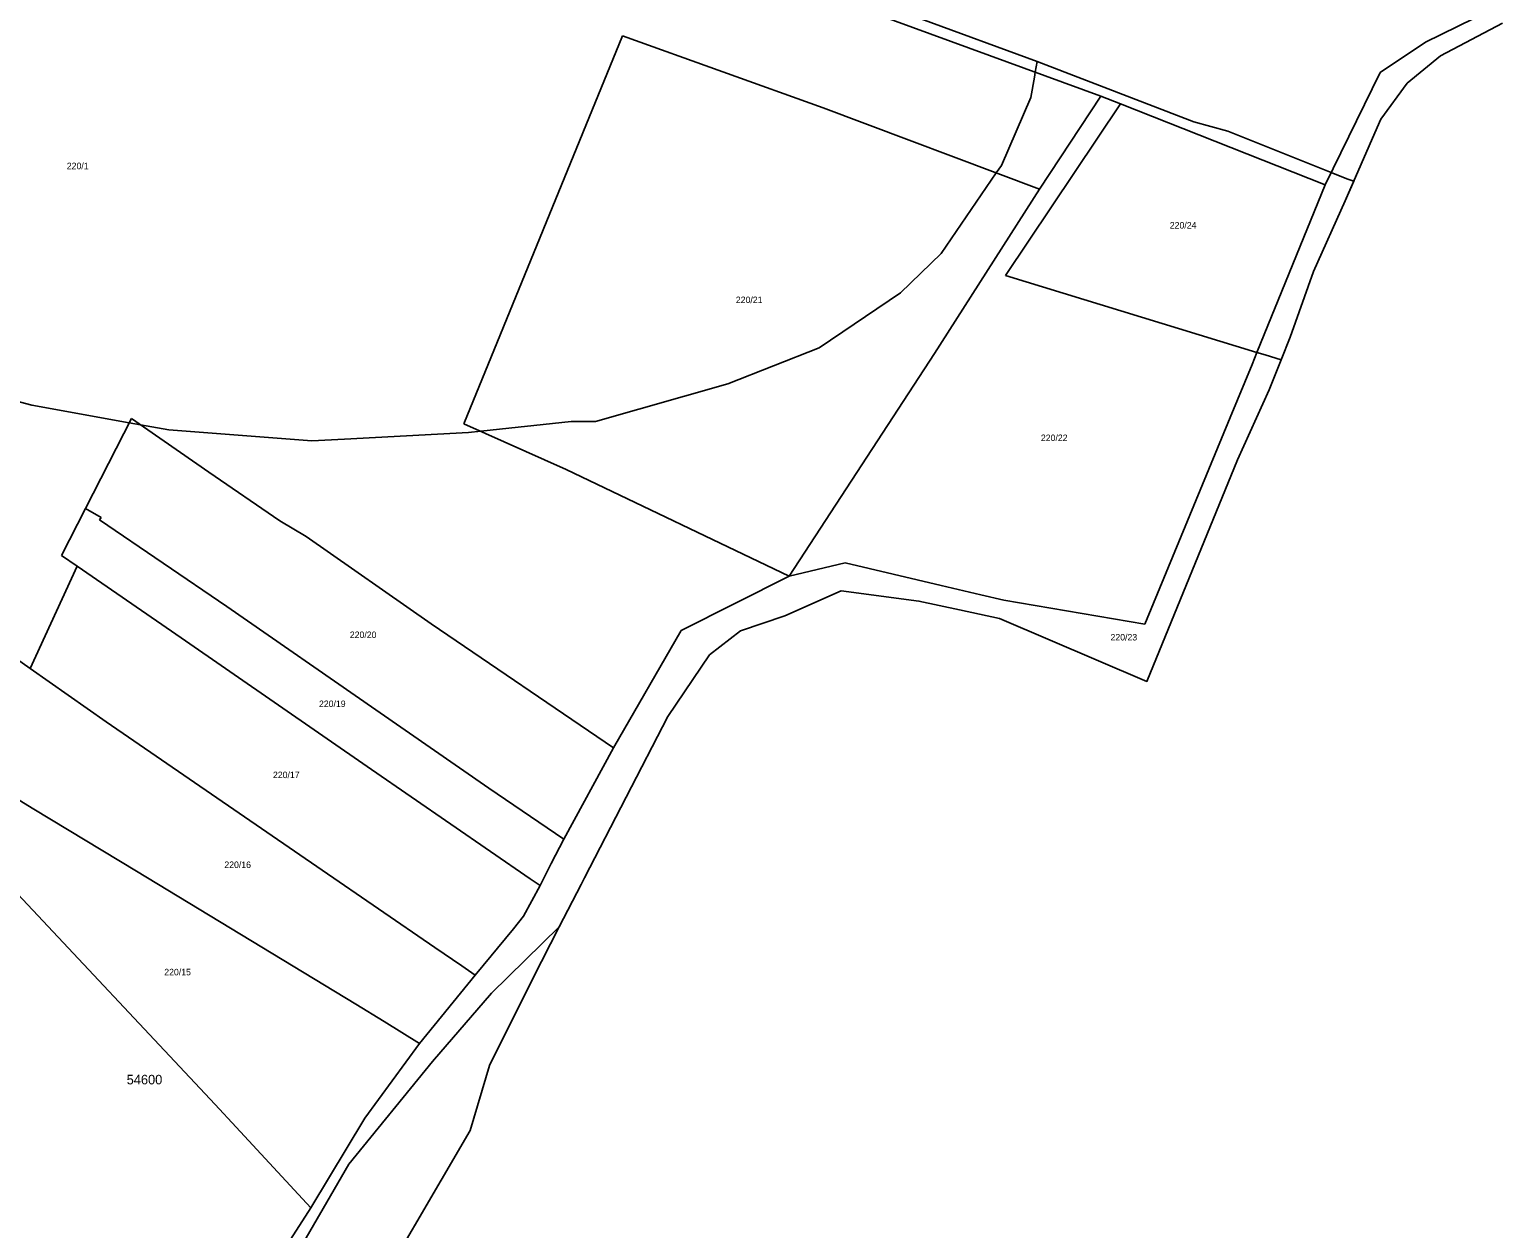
# Model space of a CAD drawing. Extents: x -749173 to -746119, y -1132678 to -1130338.
# Drawn here: x -746740.4 to -746355, y -1131280.2 to -1130967.3 of the extents above; entities that cross this region are included whole.
import ezdxf

# ---------------------------------------------------------------- set-up
doc = ezdxf.new("R2010")
doc.units = 0
for name, color, linetype in [('Vrstva 1', 7, 'Continuous'), ('Vrstva 13', 7, 'Continuous'), ('Vrstva 18', 7, 'Continuous'), ('Vrstva 52', 7, 'Continuous'), ('Vrstva 53', 7, 'Continuous'), ('Vrstva 6', 7, 'Continuous')]:
    doc.layers.add(name, color=color, linetype=linetype)

msp = doc.modelspace()

# ---------------------------------------------------------------- linework, layer by layer
at = {"layer": 'Vrstva 1'}
for points in [[(-746534.39, -1130957.75), (-746460.82, -1130984.67)], [(-746376.11, -1130970.56), (-746354.98, -1130960.28)], [(-746387.96, -1130978.54), (-746376.11, -1130970.56)], [(-746402.31, -1131007.87), (-746387.96, -1130978.54)], [(-746455.73, -1130986.67), (-746460.82, -1130984.67)], [(-746402.31, -1131007.87), (-746455.73, -1130986.67)], [(-746402.31, -1131007.87), (-746420.08, -1131051.57)], [(-746420.08, -1131051.57), (-746417.92, -1131052.24)], [(-746417.92, -1131052.24), (-746413.77, -1131053.53)]]:
    msp.add_lwpolyline(points, dxfattribs=at)
at = {"layer": 'Vrstva 13'}
for points in [[(-746372.15, -1130974.18), (-746356.02, -1130965.68)], [(-746380.86, -1130981.26), (-746372.15, -1130974.18)], [(-746387.79, -1130990.68), (-746380.86, -1130981.26)], [(-746388.73, -1130992.84), (-746387.79, -1130990.68)], [(-746397.07, -1131012), (-746388.73, -1130992.84)], [(-746405.3, -1131030.48), (-746397.07, -1131012)], [(-746411.42, -1131047.62), (-746405.3, -1131030.48)], [(-746411.42, -1131047.62), (-746413.77, -1131053.53)], [(-746413.77, -1131053.53), (-746416.87, -1131061.3)], [(-746425.17, -1131079.57), (-746416.87, -1131061.3)], [(-746448.81, -1131137.42), (-746425.17, -1131079.57)], [(-746543.27, -1131120.29), (-746528.6, -1131113.84)], [(-746528.6, -1131113.84), (-746508.31, -1131116.49)], [(-746508.31, -1131116.49), (-746497.69, -1131118.76)], [(-746554.9, -1131124.21), (-746543.27, -1131120.29)], [(-746497.69, -1131118.76), (-746487.24, -1131121.05)], [(-746487.24, -1131121.05), (-746448.81, -1131137.42)], [(-746562.93, -1131130.47), (-746554.9, -1131124.21)], [(-746573.83, -1131146.6), (-746562.93, -1131130.47)], [(-746595.54, -1131188.72), (-746573.83, -1131146.6)], [(-746602.14, -1131201.52), (-746596.42, -1131190.42)], [(-746596.42, -1131190.42), (-746595.54, -1131188.72)], [(-746609.07, -1131214.96), (-746602.14, -1131201.52)], [(-746620.38, -1131237.72), (-746609.07, -1131214.96)], [(-746625.38, -1131254.67), (-746620.38, -1131237.72)], [(-746655.09, -1131305.42), (-746625.38, -1131254.67)]]:
    msp.add_lwpolyline(points, dxfattribs=at)
at = {"layer": 'Vrstva 52'}
for points in [[(-746477.44, -1130975.62), (-746629.25, -1130919.87), (-746646.69, -1130910.12), (-746675.62, -1130899), (-746757.69, -1130871), (-746759.66, -1130869.97), (-746762.75, -1130868.37), (-746798.5, -1130856.87), (-746800.62, -1130856.87), (-746806.56, -1130868), (-746916.68, -1130816.85)], [(-746771.69, -1131056.87), (-746739.81, -1131065.37), (-746714.37, -1131069.91), (-746711.47, -1131070.43), (-746704.06, -1131071.75), (-746666.69, -1131074.62), (-746658.19, -1131074.25), (-746625.81, -1131072.5), (-746622.64, -1131072.16), (-746599.06, -1131069.62), (-746592.69, -1131069.62), (-746558.19, -1131059.75), (-746534.37, -1131050.37), (-746513.12, -1131036), (-746502.5, -1131025.75), (-746488.11, -1131004.73), (-746486.75, -1131002.75), (-746479.12, -1130985), (-746478.17, -1130979.72), (-746477.94, -1130978.41), (-746477.44, -1130975.62)], [(-746394.83, -1131006.86), (-746396.62, -1131006.25), (-746400.72, -1131004.62), (-746427.69, -1130993.87), (-746436.56, -1130991.37), (-746477.44, -1130975.62)], [(-746394.83, -1131006.86), (-746397.07, -1131012), (-746405.3, -1131030.48), (-746411.42, -1131047.62), (-746413.77, -1131053.53), (-746416.87, -1131061.3), (-746425.17, -1131079.57), (-746448.81, -1131137.42), (-746487.24, -1131121.05), (-746497.69, -1131118.76), (-746508.31, -1131116.49), (-746528.6, -1131113.84), (-746543.27, -1131120.29), (-746554.9, -1131124.21), (-746562.93, -1131130.47), (-746573.83, -1131146.6), (-746595.54, -1131188.72), (-746596.42, -1131190.42), (-746602.14, -1131201.52), (-746609.07, -1131214.96), (-746620.38, -1131237.72), (-746625.38, -1131254.67), (-746655.09, -1131305.42)]]:
    msp.add_lwpolyline(points, dxfattribs=at)
at = {"layer": 'Vrstva 6'}
for points in [[(-746627.05, -1131070.18), (-746585.61, -1130968.93)], [(-746585.61, -1130968.93), (-746533.33, -1130987.7)], [(-746485.73, -1131031.53), (-746455.73, -1130986.67)], [(-746460.82, -1130984.67), (-746476.87, -1131008.96)], [(-746533.33, -1130987.7), (-746476.87, -1131008.96)], [(-746476.87, -1131008.96), (-746504.23, -1131051.85)], [(-746420.08, -1131051.57), (-746485.73, -1131031.53)], [(-746504.23, -1131051.85), (-746542.13, -1131109.98)], [(-746421.37, -1131054.69), (-746420.08, -1131051.57)], [(-746427.09, -1131068.57), (-746421.37, -1131054.69)], [(-746449.31, -1131122.46), (-746427.09, -1131068.57)], [(-746725.78, -1131092.3), (-746713.81, -1131068.81)], [(-746713.81, -1131068.81), (-746693.57, -1131082.81)], [(-746600.31, -1131082.16), (-746627.05, -1131070.18)], [(-746693.57, -1131082.81), (-746675.09, -1131095.51)], [(-746542.13, -1131109.98), (-746600.31, -1131082.16)], [(-746732.01, -1131104.6), (-746725.78, -1131092.3)], [(-746721.71, -1131094.69), (-746725.78, -1131092.3)], [(-746722.13, -1131095.26), (-746721.71, -1131094.69)], [(-746688.92, -1131117.87), (-746722.13, -1131095.26)], [(-746675.09, -1131095.51), (-746668.21, -1131099.6)], [(-746668.21, -1131099.6), (-746635.56, -1131122.43)], [(-746727.95, -1131107.39), (-746732.01, -1131104.6)], [(-746542.13, -1131109.98), (-746527.54, -1131106.53)], [(-746527.54, -1131106.53), (-746502.52, -1131112.37)], [(-746727.95, -1131107.39), (-746740.2, -1131134.05)], [(-746700.86, -1131126.03), (-746727.95, -1131107.39)], [(-746570.38, -1131124.17), (-746542.13, -1131109.98)], [(-746502.52, -1131112.37), (-746492.12, -1131114.8)], [(-746492.12, -1131114.8), (-746486.11, -1131116.2)], [(-746650.05, -1131144.88), (-746688.92, -1131117.87)], [(-746486.11, -1131116.2), (-746449.31, -1131122.46)], [(-746635.56, -1131122.43), (-746588.04, -1131154.75)], [(-746651.17, -1131160.43), (-746700.86, -1131126.03)], [(-746588.04, -1131154.75), (-746570.38, -1131124.17)], [(-746740.2, -1131134.05), (-746745.26, -1131130.49)], [(-746720.37, -1131148), (-746740.2, -1131134.05)], [(-746620.52, -1131165.28), (-746650.05, -1131144.88)], [(-746664.01, -1131186.72), (-746720.37, -1131148)], [(-746588.04, -1131154.75), (-746600.97, -1131178.58)], [(-746759.45, -1131158.42), (-746739.3, -1131170.75)], [(-746609.75, -1131188.96), (-746651.17, -1131160.43)], [(-746600.97, -1131178.58), (-746620.52, -1131165.28)], [(-746739.3, -1131170.75), (-746712.48, -1131187)], [(-746600.97, -1131178.58), (-746604.23, -1131184.97)], [(-746712.48, -1131187), (-746655.28, -1131221.69)], [(-746634.59, -1131206.89), (-746664.01, -1131186.72)], [(-746604.23, -1131184.97), (-746607.17, -1131190.73)], [(-746746.11, -1131190.11), (-746691.93, -1131247.89)], [(-746611.45, -1131198.74), (-746607.17, -1131190.73)], [(-746607.17, -1131190.73), (-746609.75, -1131188.96)], [(-746614.12, -1131201.98), (-746611.45, -1131198.74)], [(-746624.09, -1131214.09), (-746614.12, -1131201.98)], [(-746602.14, -1131201.52), (-746619.81, -1131218.84)], [(-746627.58, -1131211.7), (-746634.59, -1131206.89)], [(-746638.6, -1131231.92), (-746624.09, -1131214.09)], [(-746624.09, -1131214.09), (-746627.58, -1131211.7)], [(-746619.81, -1131218.84), (-746635.22, -1131236.62)], [(-746655.28, -1131221.69), (-746647.87, -1131226.23)], [(-746647.87, -1131226.23), (-746638.6, -1131231.92)], [(-746638.6, -1131231.92), (-746652.91, -1131251.43)], [(-746635.22, -1131236.62), (-746657.1, -1131263.41)], [(-746691.93, -1131247.89), (-746686.45, -1131253.81)], [(-746652.91, -1131251.43), (-746667, -1131274.84)], [(-746686.45, -1131253.81), (-746667, -1131274.84)], [(-746657.1, -1131263.41), (-746686.96, -1131315.09)], [(-746667, -1131274.84), (-746724.6, -1131364.42)]]:
    msp.add_lwpolyline(points, dxfattribs=at)

# ---------------------------------------------------------------- texts
at = {"layer": 'Vrstva 18'}
for s, p in [('220/1', (-746730.66, -1131003.76)), ('220/24', (-746442.83, -1131019.25)), ('220/21', (-746556.07, -1131038.7)), ('220/22', (-746476.47, -1131074.71)), ('220/20', (-746656.81, -1131126.12)), ('220/23', (-746458.3, -1131126.75)), ('220/19', (-746664.86, -1131144.13)), ('220/17', (-746676.86, -1131162.68)), ('220/16', (-746689.55, -1131186.14)), ('220/15', (-746705.23, -1131214.15))]:
    msp.add_text(s, height=1.7, dxfattribs=at).set_placement(p)
at = {"layer": 'Vrstva 53'}
msp.add_text('54600', height=2.5, dxfattribs=at).set_placement((-746715.04, -1131242.61))

doc.saveas('drawing.dxf')
